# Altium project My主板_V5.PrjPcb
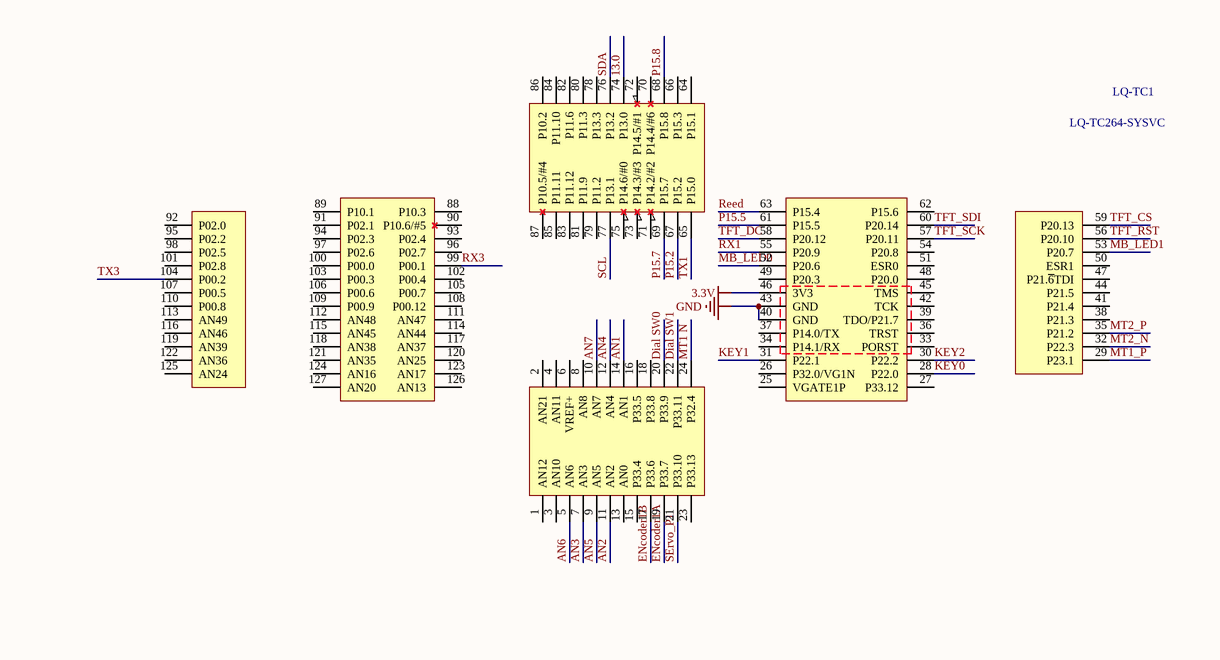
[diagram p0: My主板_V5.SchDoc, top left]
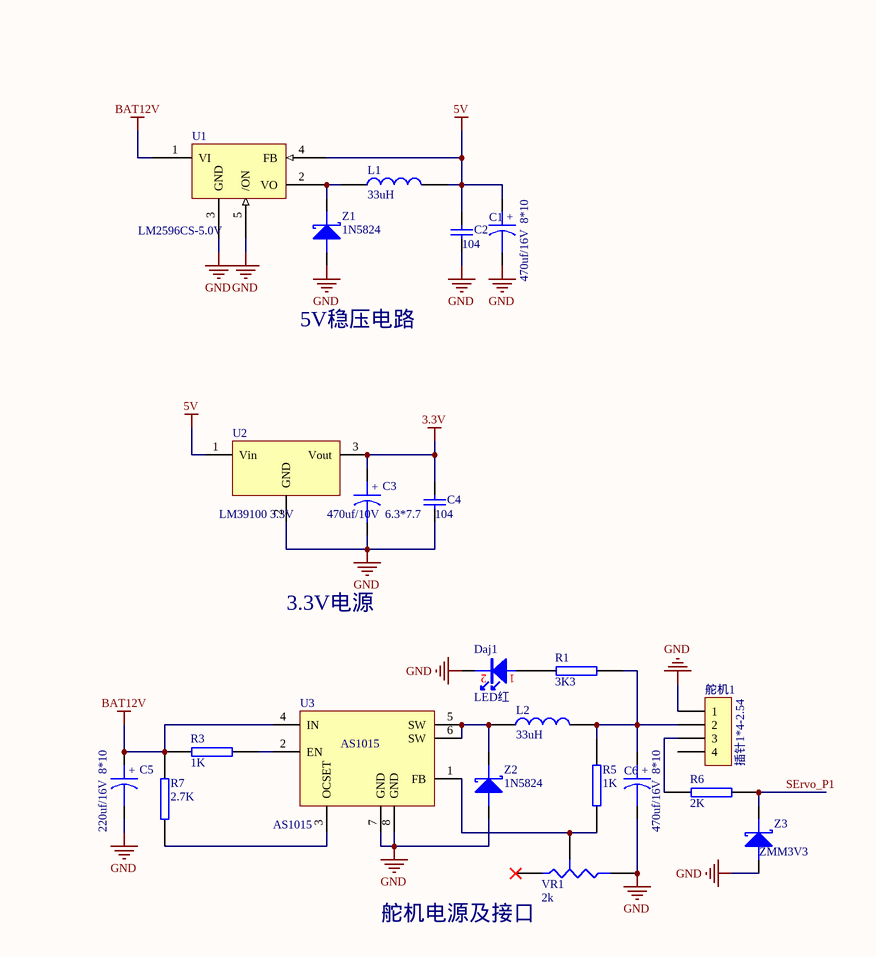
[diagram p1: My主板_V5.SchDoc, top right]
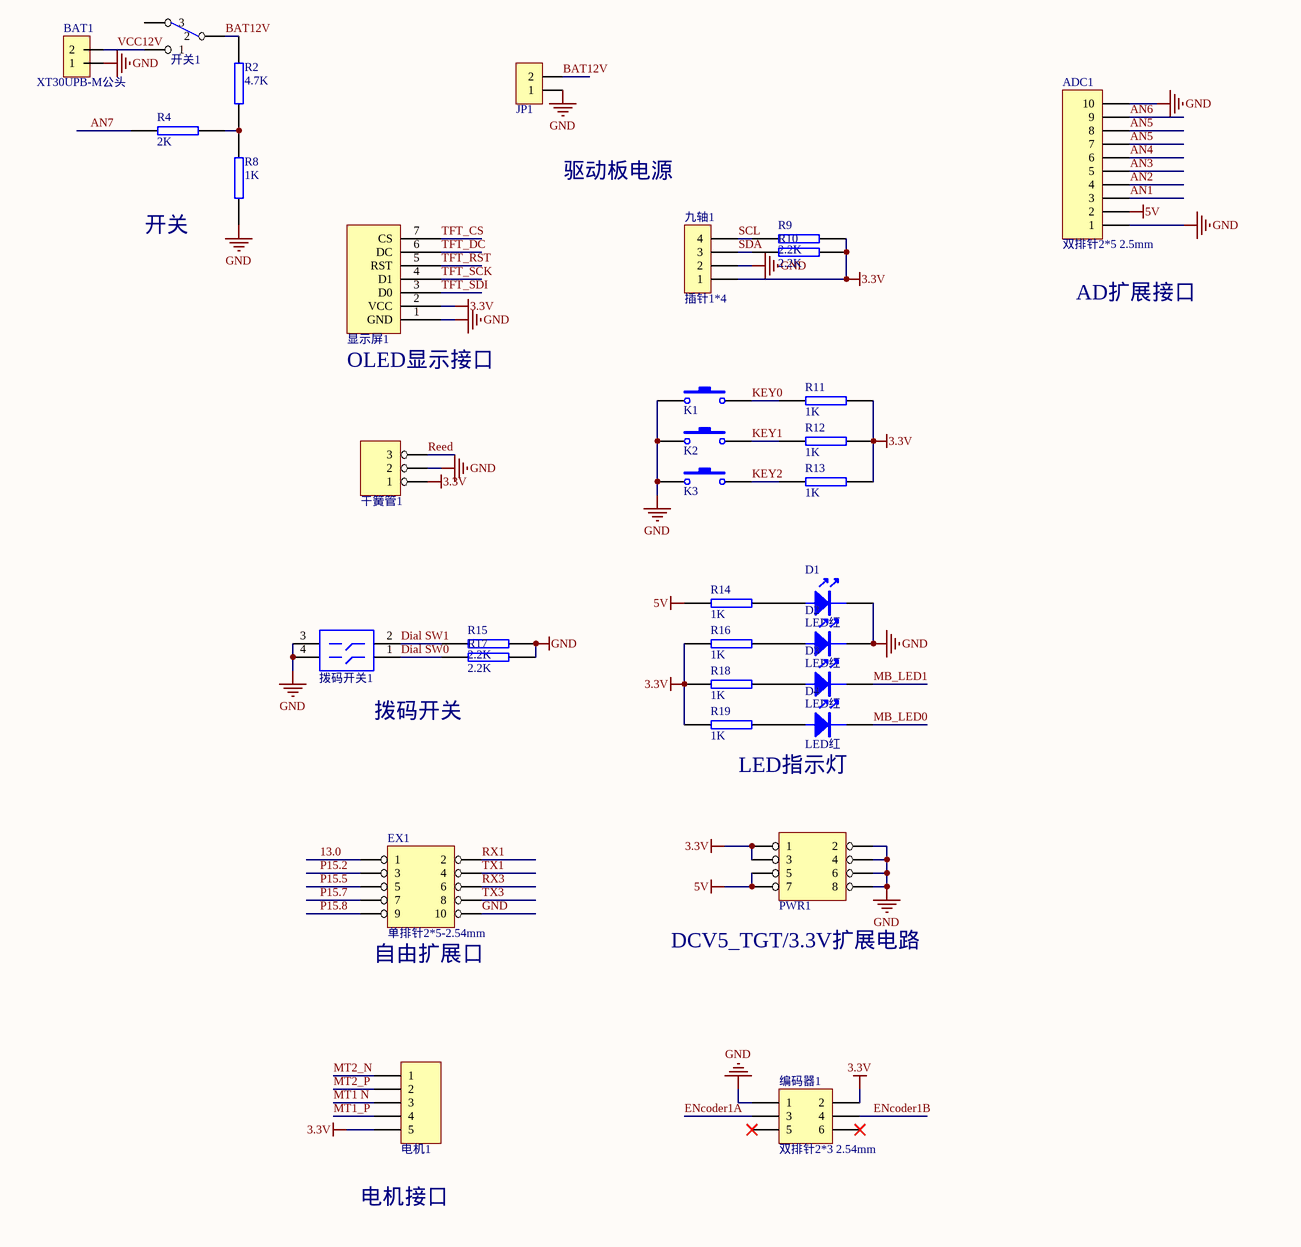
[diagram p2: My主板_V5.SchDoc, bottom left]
1 sheet, 56 parts. Net scope: global (net labels, ports and power ports of the same name join across sheets).
Board file: My主板_V5.PcbDoc

## Sheet My主板_V5.SchDoc
size A1

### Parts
ADC1  双排针2*5 2.5mm  [LQ_IDC5X2]
BAT1  XT30UPB-M公头  [LQ_XT30UPB-F]
C1  470uf/16V  8*10  [LQ_C6d3X7d7]
C2  value 104  [LQ_C0603]  (hidden comment: 104nF)
C3  470uf/10V  6.3*7.7  [LQ_C6d3X7d7]
C4  value 104  [LQ_C0603]  (hidden comment: 104nF)
C5  220uf/16V  8*10  [LQ_C6d3X7d7]
C6  470uf/16V  8*10  [LQ_C6d3X7d7]
D1  LED红  [LQ_LED0603R]
D2  LED红  [LQ_LED0603R]
D3  LED红  [LQ_LED0603R]
D4  LED红  [LQ_LED0603R]
Daj1  LED红  [LQ_LED0603R]
EX1  单排针2*5-2.54mm  [LQ_IDC5X2]
JP1  HDR-1X2  [KF301-5.0-2P]  (value not drawn)
K1  微动开关6*6*6  [LQ_BT4SMT]  (value not drawn)
K2  微动开关6*6*6  [LQ_BT4SMT]  (value not drawn)
K3  微动开关6*6*6  [LQ_BT4SMT]  (value not drawn)
L1  33uH  [LQ_L7X7]
L2  33uH  [LQ_L7X7]
LQ-TC1  LQ-TC264-SYSVC  [LQ-TC264-SYSVC-S]
PWR1  双排针4X2-2.54  [LQ_IDC4X2]  (value not drawn)
R1  3K3  [LQ_R0603]
R2  4.7K  [LQ_R0603]
R3  1K  [LQ_R0603]
R4  2K  [LQ_R0603]
R5  1K  [LQ_R0603]
R6  2K  [LQ_R0603]
R7  2.7K  [LQ_R0603]
R8  1K  [LQ_R0603]
R9  2.2K  [LQ_R0603]
R10  2.2K  [LQ_R0603]
R11  1K  [LQ_R0603]
R12  1K  [LQ_R0603]
R13  1K  [LQ_R0603]
R14  1K  [LQ_R0603]
R15  2.2K  [LQ_R0603]
R16  1K  [LQ_R0603]
R17  2.2K  [LQ_R0603]
R18  1K  [LQ_R0603]
R19  1K  [LQ_R0603]
U1  LM2596CS-5.0V  [LQ_TO-263-5]
U2  LM39100 3.3V  [SOT223_M]
U3  AS1015  [SOP8]
VR1  2k  [lq_3266]
Z1  1N5824  [LQ_1206D]
Z2  1N5824  [LQ_1206D]
Z3  ZMM3V3  [LQ_1206D]
九轴1  插针1*4  [LQ_XH254-4P]
干簧管1  XH254-3P  [LQ_XH254-3P]  (value not drawn)
开关1  KCD1-101 117S  [LQ_KCD1-101 117S]  (value not drawn)
拨码开关1  SW-DIP2  [DIP4]  (value not drawn)
显示屏1  单排座1*7-2.54  [LQ-TFT-180V33]  (value not drawn)
电机1  XH254-4P  [LQ_XH254-5P]  (value not drawn)
编码器1  双排针2*3 2.54mm  [LQ_ENCODER]
舵机1  插针1*4-2.54  [LQ_XH254-4P]

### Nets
3.3V: C3.1 C4.2 LQ-TC1.46(3V3) PWR1.1 PWR1.3 R9.1 R10.2 R11.2 R12.2 R13.2 R16.1 R18.1 R19.1 U2.3(Vout) 九轴1.1 干簧管1.1 显示屏1.2(VCC) 电机1.5 编码器1.2
5V: ADC1.2 C1.1 C2.1 L1.2 PWR1.5 PWR1.7 R14.1 U1.4(FB) U2.1(Vin)
BAT12V: C5.1 JP1.2 R2.1 R3.2 R7.1 U1.1(VI) U3.4(IN) 开关1.2
GND: ADC1.1 ADC1.10 BAT1.1 C1.2 C2.2 C3.2 C4.1 C5.2 C6.2 D1.2 D2.2 Daj1.2 EX1.10 JP1.1 K1.1 K2.1 K3.1 LQ-TC1.40(GND) LQ-TC1.43(GND) PWR1.2 PWR1.4 PWR1.6 PWR1.8 R8.2 R15.2 R17.2 U1.3(GND) U1.5(/ON) U2.2(GND) U3.7(GND) U3.8(GND) VR1.2(B) Z1.1 Z2.1 Z3.1 九轴1.2 干簧管1.2 拨码开关1.3 拨码开关1.4 显示屏1.1(GND) 编码器1.1 舵机1.1
13.0: EX1.1 LQ-TC1.74(P13.0)
AN1: ADC1.3 LQ-TC1.14(AN1)
AN2: ADC1.4 LQ-TC1.11(AN2)
AN3: ADC1.5 LQ-TC1.7(AN3)
AN4: ADC1.6 LQ-TC1.12(AN4)
AN5: ADC1.7 ADC1.8 LQ-TC1.9(AN5)
AN6: ADC1.9 LQ-TC1.5(AN6)
AN7: LQ-TC1.10(AN7) R4.1
Dial SW0: LQ-TC1.20(P33.9) R17.1 拨码开关1.1
Dial SW1: LQ-TC1.22(P33.11) R15.1 拨码开关1.2
ENcoder1A: LQ-TC1.19(P33.7) 编码器1.3
ENcoder1B: LQ-TC1.17(P33.6) 编码器1.4
KEY0: K1.2 LQ-TC1.28(P22.0) R11.1
KEY1: K2.2 LQ-TC1.31(P22.1) R12.1
KEY2: K3.2 LQ-TC1.30(P22.2) R13.1
MB_LED0: D4.2 LQ-TC1.52(P20.6)
MB_LED1: D3.2 LQ-TC1.53(P20.7)
MT1 N: LQ-TC1.24(P32.4) 电机1.3
MT1_P: LQ-TC1.29(P23.1) 电机1.4
MT2_N: LQ-TC1.32(P22.3) 电机1.1
MT2_P: LQ-TC1.35(P21.2) 电机1.2
P15.2: EX1.3 LQ-TC1.67(P15.2)
P15.5: EX1.5 LQ-TC1.61(P15.5)
P15.7: EX1.7 LQ-TC1.69(P15.7)
P15.8: EX1.9 LQ-TC1.68(P15.8)
Reed: LQ-TC1.63(P15.4) 干簧管1.3
RX1: EX1.2 LQ-TC1.55(P20.9)
RX3: EX1.6 LQ-TC1.99(P00.1)
SCL: LQ-TC1.77(P13.1) R9.2 九轴1.4
SDA: LQ-TC1.76(P13.2) R10.1 九轴1.3
SErvo_P1: LQ-TC1.21(P33.10) R6.1 Z3.2
TFT_CS: LQ-TC1.59(P20.13) 显示屏1.7(CS)
TFT_DC: LQ-TC1.58(P20.12) 显示屏1.6(DC)
TFT_RST: LQ-TC1.56(P20.10) 显示屏1.5(RST)
TFT_SCK: LQ-TC1.57(P20.11) 显示屏1.4(D1)
TFT_SDI: LQ-TC1.60(P20.14) 显示屏1.3(D0)
TX1: EX1.4 LQ-TC1.65(P15.0)
TX3: EX1.8 LQ-TC1.104(P00.2)
VCC12V: BAT1.2 开关1.1
NetC6_1: C6.1 L2.2 R1.2 R5.2 舵机1.2
NetD1_1: D1.1 R14.2
NetD2_1: D2.1 R16.2
NetD3_1: D3.1 R18.2
NetD4_1: D4.1 R19.2
NetDaj1_1: Daj1.1 R1.1
NetL1_1: L1.1 U1.2(VO) Z1.2
NetL2_1: L2.1 U3.5(SW) U3.6(SW) Z2.2
NetR2_2: R2.2 R4.2 R8.1
NetR3_1: R3.1 U3.2(EN)
NetR5_1: R5.1 U3.1(FB) VR1.3(TAP)
NetR6_2: R6.2 舵机1.3
NetR7_2: R7.2 U3.3(OCSET)

Not connected (* = marked no-connect by the designer): LQ-TC1 1(AN12) 2(AN21) 3(AN10) 4(AN11) 6(VREF+) 8(AN8) 13(AN0) 15(P33.4) 16(P33.5) 18(P33.8) 23(P33.13) 25(VGATE1P) 26(P32.0/VG1N) 27(P33.12) 33(PORST) 34(P14.1/RX) 36(TRST) 37(P14.0/TX) 38(P21.3) 39(TDO/P21.7) 41(P21.4) 42(TCK) 44(P21.5) 45(TMS) 47(P21.~{6}TDI) 48(P20.0) 49(P20.3) 50(ESR1) 51(ESR0) 54(P20.8) 62(P15.6) 64(P15.1) 66(P15.3) 70(P14.4/#6) 71(P14.2/#2) 72(P14.5/#1) 73(P14.3/#3) 75(P14.6/#0) 78(P13.3) 79(P11.2) 80(P11.3) 81(P11.9) 82(P11.6) 83(P11.12) 84(P11.10) 85(P11.11) 86(P10.2) 87(P10.5/#4) 88(P10.3) 89(P10.1) 90(P10.6/#5) 91(P02.1) 92(P02.0) 93(P02.4) 94(P02.3) 95(P02.2) 96(P02.7) 97(P02.6) 98(P02.5) 100(P00.0) 101(P02.8) 102(P00.4) 103(P00.3) 105(P00.7) 106(P00.6) 107(P00.5) 108(P00.12) 109(P00.9) 110(P00.8) 111(AN47) 112(AN48) 113(AN49) 114(AN44) 115(AN45) 116(AN46) 117(AN37) 118(AN38) 119(AN39) 120(AN25) 121(AN35) 122(AN36) 123(AN17) 124(AN16) 125(AN24) 126(AN13) 127(AN20); VR1 1(A)*; 开关1 3; 编码器1 5* 6*; 舵机1 4

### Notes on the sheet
- 5V稳压电路
- 3.3V电源
- 驱动板电源
- 开关
- AD扩展接口
- 舵机电源及接口
- (near 显示屏1) OLED显示接口
- 拨码开关
- LED指示灯
- (near EX1) 自由扩展口
- (near PWR1) DCV5_TGT/3.3V扩展电路
- 电机接口

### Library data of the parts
ADC1 = CON10: Connector
BAT1 = LQ_PIN2: Jumper
C1 C3 C5 C6 = CAPACITOR POL: Capacitor
C2 C4 = Cap: Capacitor
D1-D4 = LED
Daj1 = LQ_LED
EX1 = HEADER 5X2
JP1 = Header 2_1: 2P接插件; 版权归属: 源创客
K1-K3 = 微动开关
L1 L2 = INDUCTOR
PWR1 = HEADER 4X2
R1-R19 = RES2
U1 = LM2575T
U2 = VOLTREG
VR1 = RESISTOR TAPPED
Z1-Z3 = LQ_D: Schottky Diode
九轴1 舵机1 = CON4: Connector
干簧管1 = HEADER 3
开关1 = LQ_SWMTS102
显示屏1 = LQ_OLED128X64
电机1 = Header 5: Header, 5-Pin
编码器1 = Header 3X2: Header, 3-Pin, Dual row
